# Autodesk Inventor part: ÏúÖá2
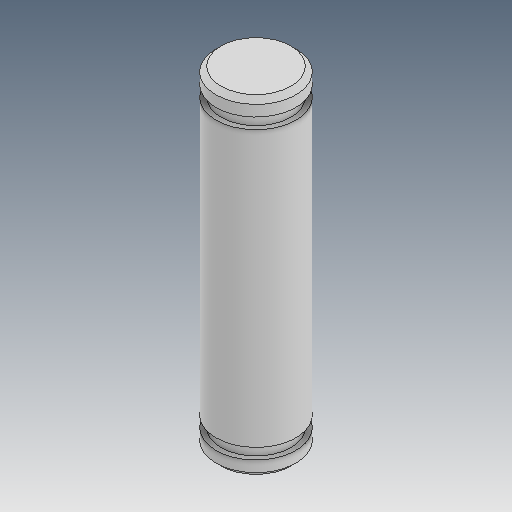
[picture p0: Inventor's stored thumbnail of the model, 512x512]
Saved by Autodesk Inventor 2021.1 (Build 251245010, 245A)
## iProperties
Created: 2019-04
Part Number: ÏúÖá2
Material: Ogólny
Document SubType Name: Modeling
Designer: user
Density: 1 g/cm^3
Appearance: Domyślna
Author: user
Revision Number: ÈÎºÎ
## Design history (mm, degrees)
feature "ÊäÈë1"
node "Bryła1"
